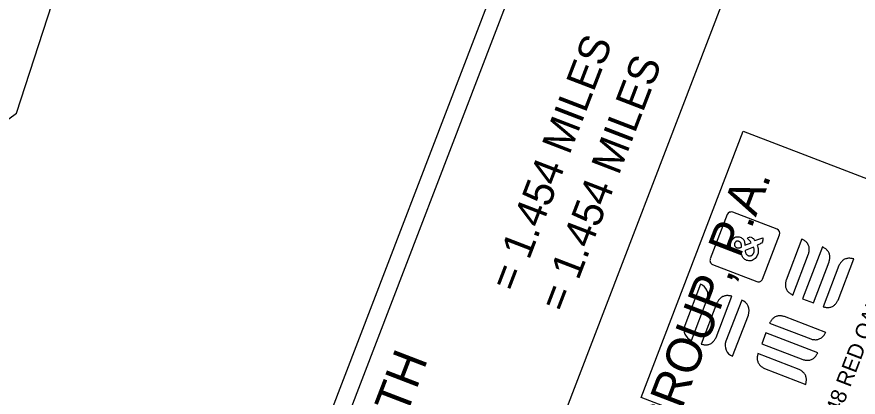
# Model space of a CAD drawing. Extents: x 1015221 to 1064345, y 619216 to 647967.
# Drawn here: x 1023380 to 1025328, y 638817 to 639697 of the extents above; entities that cross this region are included whole.
import ezdxf

# ---------------------------------------------------------------- set-up
doc = ezdxf.new("R2010")
doc.units = 0
for name, color, linetype in [('Old_Level_8', 7, 'Continuous'), ('Scratch_Level_2', 7, 'Continuous'), ('Sheet Data Field CELL', 7, 'Continuous'), ('Sheet Data Text CELL', 7, 'Continuous'), ('Sheet Title CELL', 7, 'Continuous')]:
    doc.layers.add(name, color=color, linetype=linetype)

msp = doc.modelspace()

# ---------------------------------------------------------------- linework, layer by layer
at = {"layer": 'Scratch_Level_2'}
msp.add_lwpolyline([(1020895.4, 635853.8), (1022473.8, 638805.7), (1023379.2, 639473.6), (1023843, 640900.1), (1023637.3, 641036.3), (1023148.3, 642068.8), (1023188.2, 643043.1), (1024411.5, 644926.1), (1023531, 645498.1), (1022160.6, 643388.7), (1022151.2, 643382.8), (1022046.3, 641942.6), (1021939, 640556.9), (1021513.5, 639679.1), (1020439.2, 638632.2), (1020121.4, 637513.2), (1020059.5, 637223.8), (1019861.3, 636035.8)], close=True, dxfattribs=at)
at = {"layer": 'Sheet Data Text CELL'}
for p, q in [((1025025.2, 639239), (1024985.7, 639136.4)), ((1025140.4, 639205.2), (1025037.7, 639244.7)), ((1025106.5, 639090), (1025146, 639192.6)), ((1024991.3, 639123.8), (1025094, 639084.4))]:
    msp.add_line(p, q, dxfattribs=at)
for points in [[(1024825.5, 638816.3), (1025062.2, 639432.5), (1025713.1, 639182.4), (1025476.4, 638566.2)], [(1025052.1, 639177.2), (1025051.5, 639177.3), (1025050.9, 639177.4), (1025050.4, 639177.5), (1025049.8, 639177.6), (1025049.2, 639177.7), (1025048.6, 639177.7), (1025048, 639177.6), (1025047.5, 639177.5), (1025046.9, 639177.3), (1025046.3, 639177.1), (1025045.8, 639176.8), (1025045.3, 639176.5), (1025044.8, 639176.2), (1025044.4, 639175.8), (1025044, 639175.3), (1025043.6, 639174.9), (1025043.3, 639174.4), (1025043, 639173.9), (1025042.7, 639173.3), (1025042.5, 639172.8), (1025042.3, 639172.2), (1025042.1, 639171.7), (1025042, 639171.1), (1025041.9, 639170.5), (1025041.9, 639169.9), (1025041.9, 639169.3), (1025042, 639168.7), (1025042.1, 639168.1), (1025042.2, 639167.6), (1025042.4, 639167), (1025042.7, 639166.4), (1025042.9, 639165.9), (1025043.3, 639165.4), (1025043.7, 639165), (1025044.1, 639164.6), (1025044.5, 639164.2), (1025045, 639163.9), (1025045.5, 639163.6), (1025046, 639163.3), (1025046.5, 639163), (1025047.1, 639162.7), (1025047.2, 639162.6), (1025047.7, 639162.5), (1025048.2, 639162.4), (1025048.7, 639162.2), (1025049.1, 639162.1), (1025049.6, 639162), (1025050.1, 639162), (1025050.6, 639161.9), (1025051.1, 639161.9), (1025051.5, 639162), (1025052, 639162), (1025052.5, 639162.1), (1025053, 639162.2), (1025053.5, 639162.3), (1025054, 639162.4), (1025054.4, 639162.5), (1025054.9, 639162.7), (1025055.4, 639162.8), (1025055.8, 639162.9), (1025056.3, 639163.1), (1025057.2, 639163.4), (1025058.1, 639163.8), (1025058.1, 639165.1), (1025058.1, 639165.8), (1025058.1, 639166.4), (1025058, 639167.1), (1025058, 639167.8), (1025057.9, 639168.5), (1025057.8, 639169.1), (1025057.7, 639169.8), (1025057.6, 639170.5), (1025057.4, 639171.1), (1025057.2, 639171.8), (1025057, 639172.5), (1025056.7, 639173.1), (1025056.4, 639173.7), (1025056, 639174.2), (1025055.6, 639174.7), (1025055.1, 639175.2), (1025054.6, 639175.6), (1025054, 639176), (1025053.5, 639176.4), (1025052.9, 639176.7), (1025052.3, 639177.1)]]:
    msp.add_lwpolyline(points, close=True, dxfattribs=at)
for points in [[(1025025.2, 639239), (1025025.2, 639239), (1024985.7, 639136.4)], [(1025033.2, 639245.2), (1025033.2, 639245.2), (1025032.5, 639245.1), (1025031.9, 639245), (1025031.2, 639244.8), (1025030.6, 639244.6), (1025030, 639244.3), (1025029.4, 639244), (1025028.8, 639243.7), (1025028.3, 639243.3), (1025028.2, 639243.1)], [(1025140.4, 639205.2), (1025037.7, 639244.7)], [(1025094.5, 639168.3), (1025095.3, 639165.8), (1025096.1, 639163.3), (1025096.7, 639160.7), (1025097, 639158.1), (1025097.1, 639155.5), (1025096.8, 639152.8), (1025096.4, 639150.2), (1025095.7, 639147.7), (1025094.8, 639145.2), (1025093.6, 639142.8), (1025092.2, 639140.6), (1025089.6, 639137.5), (1025087.6, 639135.7), (1025085.4, 639134.2), (1025083, 639133), (1025080.5, 639132.3), (1025077.9, 639132), (1025075.3, 639132.2), (1025072.7, 639132.6), (1025070, 639133.1), (1025067.9, 639134.2), (1025066.1, 639135.3), (1025064.3, 639136.5), (1025062.8, 639138), (1025061.5, 639139.6), (1025060.3, 639141.5), (1025059.5, 639143.5), (1025058.8, 639145.5), (1025058.3, 639147.6), (1025058, 639149.7), (1025057.8, 639151.8), (1025056.4, 639152.5), (1025054.5, 639152.1), (1025052.6, 639151.7), (1025050.6, 639151.5), (1025048.7, 639151.5), (1025046.7, 639151.7), (1025044.8, 639152.2), (1025042.9, 639152.7), (1025041.6, 639153.5), (1025039.3, 639154.9), (1025037.2, 639156.5), (1025035.5, 639158.4), (1025034.1, 639160.6), (1025033.2, 639163.1), (1025032.7, 639165.8), (1025032.5, 639168.4), (1025032.7, 639171.1), (1025033.2, 639173.7), (1025034, 639176.2), (1025035.1, 639178.6), (1025036.5, 639180.8), (1025038.1, 639182.9), (1025040.1, 639184.7), (1025042.3, 639186.2), (1025044.8, 639187.3), (1025047.3, 639187.8), (1025049.9, 639187.8), (1025052.5, 639187.5), (1025055.2, 639186.9), (1025057.2, 639185.9), (1025059, 639184.8), (1025060.6, 639183.5), (1025062.1, 639182.1), (1025063.3, 639180.4), (1025064.2, 639178.5), (1025064.9, 639176.5), (1025065.4, 639174.5), (1025065.8, 639172.4), (1025066, 639170.4), (1025066.1, 639168.3), (1025080.9, 639173.7), (1025079.7, 639175.2), (1025078.6, 639176.7), (1025077.4, 639178.2), (1025076.2, 639179.6), (1025075, 639181.1), (1025073.7, 639182.5), (1025072.4, 639183.9), (1025072.7, 639185.5), (1025073.9, 639186.2), (1025076.4, 639187.1), (1025078.5, 639187.3), (1025080.5, 639186.9), (1025082.4, 639186.1), (1025084, 639184.9), (1025085.6, 639183.5), (1025086.7, 639182), (1025087.8, 639180.5), (1025088.9, 639178.9), (1025107.5, 639185.1)], [(1025106.5, 639090), (1025146, 639192.6)], [(1025052.1, 639177.2), (1025051.5, 639177.3), (1025050.9, 639177.4), (1025050.4, 639177.5), (1025049.8, 639177.6), (1025049.2, 639177.7), (1025048.6, 639177.7), (1025048, 639177.6), (1025047.5, 639177.5), (1025046.9, 639177.3), (1025046.3, 639177.1), (1025045.8, 639176.8), (1025045.3, 639176.5), (1025044.8, 639176.2), (1025044.4, 639175.8), (1025044, 639175.3), (1025043.6, 639174.9), (1025043.3, 639174.4), (1025043, 639173.9), (1025042.7, 639173.3), (1025042.5, 639172.8), (1025042.3, 639172.2), (1025042.1, 639171.7), (1025042, 639171.1), (1025041.9, 639170.5), (1025041.9, 639169.9), (1025041.9, 639169.3), (1025042, 639168.7), (1025042.1, 639168.1), (1025042.2, 639167.6), (1025042.4, 639167), (1025042.7, 639166.4), (1025042.9, 639165.9), (1025043.3, 639165.4), (1025043.7, 639165), (1025044.1, 639164.6), (1025044.5, 639164.2), (1025045, 639163.9), (1025045.5, 639163.6), (1025046, 639163.3), (1025046.5, 639163), (1025047.1, 639162.7), (1025047.2, 639162.6), (1025047.7, 639162.5), (1025048.2, 639162.4), (1025048.7, 639162.2), (1025049.1, 639162.1), (1025049.6, 639162), (1025050.1, 639162), (1025050.6, 639161.9), (1025051.1, 639161.9), (1025051.5, 639162), (1025052, 639162), (1025052.5, 639162.1), (1025053, 639162.2), (1025053.5, 639162.3), (1025054, 639162.4), (1025054.4, 639162.5), (1025054.9, 639162.7), (1025055.4, 639162.8), (1025055.8, 639162.9), (1025056.3, 639163.1), (1025057.2, 639163.4), (1025058.1, 639163.8), (1025058.1, 639165.1), (1025058.1, 639165.8), (1025058.1, 639166.4), (1025058, 639167.1), (1025058, 639167.8), (1025057.9, 639168.5), (1025057.8, 639169.1), (1025057.7, 639169.8), (1025057.6, 639170.5), (1025057.4, 639171.1), (1025057.2, 639171.8), (1025057, 639172.5), (1025056.7, 639173.1), (1025056.4, 639173.7), (1025056, 639174.2), (1025055.6, 639174.7), (1025055.1, 639175.2), (1025054.6, 639175.6), (1025054, 639176), (1025053.5, 639176.4), (1025052.9, 639176.7), (1025052.3, 639177.1), (1025052.1, 639177.2)], [(1025107.6, 639184.3), (1025107.8, 639182.1), (1025107.7, 639179.9), (1025107.1, 639177.7), (1025106.5, 639176.3), (1025104.2, 639173.4), (1025102.4, 639172), (1025100.5, 639170.8), (1025094.5, 639168.3)], [(1025107.5, 639185.1), (1025107.6, 639184.3)], [(1025211.8, 639171.2), (1025210.8, 639172.7), (1025209.7, 639174.1), (1025208.4, 639175.5), (1025207.1, 639176.7), (1025205.7, 639177.9), (1025204.3, 639178.9), (1025202.8, 639179.9), (1025201.2, 639180.9), (1025199.6, 639181.8), (1025198, 639182.8), (1025161.4, 639087.5), (1025161.1, 639085.7), (1025160.7, 639083.9), (1025160.4, 639082.1), (1025160.1, 639080.3), (1025159.9, 639078.5), (1025159.8, 639076.7), (1025159.9, 639074.9), (1025160.1, 639073.1), (1025160.4, 639071.3), (1025160.9, 639069.5), (1025161.5, 639067.8), (1025162.2, 639066.1), (1025163.1, 639064.5), (1025164.1, 639062.9), (1025165.2, 639061.5), (1025166.4, 639060.1), (1025167.8, 639058.9), (1025169.1, 639057.8), (1025170.6, 639056.7), (1025172.1, 639055.7), (1025173.7, 639054.7), (1025175.3, 639053.8), (1025176.8, 639052.9), (1025213.5, 639148.1), (1025213.8, 639149.9), (1025214.2, 639151.7), (1025214.5, 639153.5), (1025214.8, 639155.3), (1025215, 639157.1), (1025215, 639158.9), (1025215, 639160.7), (1025214.8, 639162.5), (1025214.5, 639164.3), (1025214, 639166.1), (1025213.4, 639167.8), (1025212.6, 639169.5), (1025211.8, 639171.2)], [(1025073.8, 639144.2), (1025074.6, 639144), (1025075.3, 639143.9), (1025076.1, 639143.7), (1025076.8, 639143.7), (1025077.5, 639143.6), (1025078.2, 639143.6), (1025079, 639143.7), (1025080.4, 639144.1), (1025081.7, 639144.7), (1025082.9, 639145.6), (1025083.5, 639146.1), (1025084, 639146.6), (1025084.5, 639147.2), (1025085, 639147.8), (1025085.4, 639148.4), (1025085.8, 639149), (1025086.1, 639149.6), (1025086.5, 639150.3), (1025086.7, 639151), (1025087, 639151.7), (1025087.2, 639152.4), (1025087.4, 639153.1), (1025087.5, 639153.8), (1025087.6, 639154.6), (1025087.7, 639155.3), (1025087.7, 639156), (1025087.7, 639156.8), (1025087.6, 639157.5), (1025087.6, 639158.2), (1025087.5, 639159), (1025087.3, 639159.7), (1025087, 639161.1), (1025086.6, 639162.5), (1025086.1, 639163.9), (1025066.6, 639156.3), (1025066.8, 639155), (1025066.9, 639153.7), (1025067.2, 639152.5), (1025067.5, 639151.2), (1025067.9, 639150), (1025068.5, 639148.8), (1025069.1, 639147.7), (1025070, 639146.7), (1025070.9, 639145.9), (1025072, 639145.2), (1025072.5, 639144.8), (1025073.1, 639144.5), (1025073.8, 639144.2)], [(1025254.8, 639158.4), (1025253.4, 639159.6), (1025251.9, 639160.6), (1025250.4, 639161.6), (1025248.9, 639162.6), (1025247.3, 639163.5), (1025245.7, 639164.5), (1025199.5, 639044.2), (1025224.5, 639034.6), (1025261.1, 639129.8), (1025261.5, 639131.6), (1025261.8, 639133.4), (1025262.2, 639135.2), (1025262.4, 639137), (1025262.6, 639138.8), (1025262.7, 639140.6), (1025262.6, 639142.4), (1025262.5, 639144.2), (1025262.1, 639146), (1025261.7, 639147.8), (1025261, 639149.5), (1025260.3, 639151.2), (1025259.4, 639152.8), (1025258.4, 639154.4), (1025257.3, 639155.8), (1025256.1, 639157.2), (1025254.8, 639158.4)], [(1024985.3, 639130.7), (1024985.4, 639130.5), (1024985.5, 639129.9), (1024985.8, 639129.3), (1024986, 639128.6), (1024986.4, 639128), (1024986.7, 639127.5), (1024986.9, 639127.3)], [(1025309.3, 639138.1), (1025307.5, 639138.1), (1025305.7, 639138.1), (1025303.9, 639137.9), (1025302.1, 639137.6), (1025300.4, 639137.1), (1025298.6, 639136.5), (1025296.9, 639135.7), (1025295.3, 639134.9), (1025293.8, 639133.9), (1025292.3, 639132.8), (1025291, 639131.5), (1025289.8, 639130.2), (1025288.6, 639128.8), (1025287.6, 639127.4), (1025286.5, 639125.9), (1025285.6, 639124.3), (1025284.6, 639122.7), (1025283.7, 639121.1), (1025247.1, 639025.9), (1025248.9, 639025.5), (1025250.7, 639025.1), (1025252.5, 639024.8), (1025254.3, 639024.5), (1025256.1, 639024.3), (1025257.9, 639024.3), (1025259.7, 639024.3), (1025261.5, 639024.5), (1025263.3, 639024.8), (1025265.1, 639025.3), (1025266.8, 639025.9), (1025268.5, 639026.7), (1025270.1, 639027.5), (1025271.7, 639028.5), (1025273.1, 639029.6), (1025274.5, 639030.9), (1025275.7, 639032.2), (1025276.8, 639033.6), (1025277.9, 639035), (1025278.9, 639036.5), (1025279.9, 639038.1), (1025280.8, 639039.7), (1025281.7, 639041.3), (1025318.3, 639136.5), (1025316.5, 639136.9), (1025314.7, 639137.3), (1025312.9, 639137.6), (1025311.1, 639137.9), (1025309.3, 639138.1)], [(1024991.3, 639123.8), (1025094, 639084.4)], [(1024963.3, 639078), (1024926.7, 638982.7)], [(1025019.8, 639051.1), (1025018, 639050.7), (1025016.3, 639050), (1025014.6, 639049.3), (1025012.9, 639048.4), (1025011.4, 639047.4), (1025010, 639046.3), (1025008.6, 639045.1), (1025007.4, 639043.8), (1025006.2, 639042.4), (1025005.2, 639040.9), (1025004.2, 639039.4), (1025003.2, 639037.9), (1025002.3, 639036.3), (1025001.3, 639034.7), (1024964.7, 638939.4), (1024966.5, 638939), (1024968.3, 638938.7), (1024970.1, 638938.3), (1024971.9, 638938.1), (1024973.7, 638937.9), (1024975.5, 638937.8), (1024977.3, 638937.8), (1024979.1, 638938), (1024980.9, 638938.4), (1024982.7, 638938.8), (1024984.4, 638939.5), (1024986.1, 638940.2), (1024987.7, 638941.1), (1024989.3, 638942.1), (1024990.7, 638943.2), (1024992.1, 638944.4), (1024993.3, 638945.7), (1024994.4, 638947.1), (1024995.5, 638948.6), (1024996.5, 638950.1), (1024997.5, 638951.6), (1024998.4, 638953.2), (1024999.4, 638954.8), (1025036, 639050.1), (1025034.2, 639050.5), (1025032.4, 639050.8), (1025030.6, 639051.2), (1025028.8, 639051.4), (1025027, 639051.6), (1025025.2, 639051.7), (1025023.4, 639051.6), (1025021.6, 639051.5), (1025019.8, 639051.1)], [(1024942.1, 638948.1), (1024978.7, 639043.4)], [(1025058.6, 639041.4), (1025022, 638946.1)], [(1025037.4, 638911.5), (1025074, 639006.8)], [(1025157.8, 639003.3), (1025156, 639003.7), (1025154.2, 639004), (1025152.4, 639004.3), (1025150.6, 639004.6), (1025148.8, 639004.8), (1025147, 639004.9), (1025145.2, 639004.8), (1025143.4, 639004.6), (1025141.6, 639004.3), (1025139.8, 639003.8), (1025138.1, 639003.2), (1025136.4, 639002.5), (1025134.8, 639001.6), (1025133.2, 639000.6), (1025131.8, 638999.5), (1025130.5, 638998.3), (1025129.2, 638997), (1025128.1, 638995.6), (1025127, 638994.1), (1025126, 638992.6), (1025125, 638991), (1025124.1, 638989.5), (1025123.2, 638987.9), (1025218.5, 638951.3), (1025220.3, 638950.9), (1025222.1, 638950.5), (1025223.9, 638950.2), (1025225.7, 638949.9), (1025227.5, 638949.8), (1025229.3, 638949.7), (1025231.1, 638949.7), (1025232.8, 638949.9), (1025234.6, 638950.2), (1025236.4, 638950.7), (1025238.2, 638951.3), (1025239.8, 638952.1), (1025241.5, 638952.9), (1025243, 638953.9), (1025244.5, 638955.1), (1025245.8, 638956.3), (1025247, 638957.6), (1025248.2, 638959), (1025249.2, 638960.4), (1025250.2, 638961.9), (1025251.2, 638963.5), (1025252.2, 638965.1), (1025253.1, 638966.7), (1025157.8, 639003.3)], [(1025114.5, 638965.2), (1025104.9, 638940.2), (1025200.1, 638903.6), (1025201.9, 638903.2), (1025203.7, 638902.9), (1025205.5, 638902.6), (1025207.3, 638902.3), (1025209.1, 638902.1), (1025210.9, 638902), (1025212.7, 638902.1), (1025214.5, 638902.3), (1025216.3, 638902.6), (1025218.1, 638903.1), (1025219.9, 638903.7), (1025221.5, 638904.4), (1025223.2, 638905.3), (1025224.7, 638906.3), (1025226.2, 638907.4), (1025227.5, 638908.6), (1025228.7, 638909.9), (1025229.9, 638911.3), (1025230.9, 638912.8), (1025231.9, 638914.3), (1025232.9, 638915.9), (1025233.8, 638917.4), (1025234.8, 638919), (1025114.5, 638965.2)], [(1025096.2, 638917.6), (1025095.8, 638915.8), (1025095.4, 638914), (1025095.1, 638912.2), (1025094.8, 638910.4), (1025094.7, 638908.6), (1025094.6, 638906.8), (1025094.6, 638905), (1025094.8, 638903.2), (1025095.1, 638901.4), (1025095.6, 638899.6), (1025096.2, 638897.9), (1025097, 638896.2), (1025097.9, 638894.6), (1025098.9, 638893), (1025100, 638891.6), (1025101.2, 638890.3), (1025102.5, 638889), (1025103.9, 638887.9), (1025105.3, 638886.8), (1025106.9, 638885.8), (1025108.4, 638884.8), (1025110, 638883.9), (1025111.6, 638883), (1025206.9, 638846.4), (1025207.2, 638848.2), (1025207.6, 638850), (1025207.9, 638851.8), (1025208.2, 638853.6), (1025208.4, 638855.4), (1025208.4, 638857.2), (1025208.4, 638859), (1025208.2, 638860.8), (1025207.9, 638862.6), (1025207.4, 638864.3), (1025206.8, 638866.1), (1025206.1, 638867.8), (1025205.2, 638869.4), (1025204.2, 638870.9), (1025203.1, 638872.4), (1025201.9, 638873.7), (1025200.5, 638874.9), (1025199.2, 638876.1), (1025197.7, 638877.2), (1025196.2, 638878.2), (1025194.6, 638879.1), (1025193, 638880.1), (1025191.5, 638881), (1025096.2, 638917.6)]]:
    msp.add_lwpolyline(points, dxfattribs=at)
for centre, radius, start, end in [((1025034.3, 639235.5), 9.77, 69.4028, 158.8148), ((1025034.3, 639235.5), 9.77, 69.4028, 158.8148), ((1025136.9, 639196.1), 9.77, 339.1512, 68.5632), ((1025136.9, 639196.1), 9.77, 339.1512, 68.5632), ((1024994.8, 639132.9), 9.7, 158.9773, 248.983), ((1024994.8, 639132.9), 9.7, 158.9773, 248.983), ((1025097.5, 639093.4), 9.7, 248.983, 338.9887), ((1025097.5, 639093.4), 9.7, 248.983, 338.9887), ((1024953.7, 639053), 26.8, 338.983, 68.983), ((1025049, 639016.4), 26.8, 338.983, 68.983), ((1024951.7, 638973.1), 26.8, 158.983, 248.983), ((1025047, 638936.5), 26.8, 158.983, 248.983)]:
    msp.add_arc(centre, radius, start, end, dxfattribs=at)
at = {"layer": 'Sheet Title CELL'}
for p, q in [((1022495.1, 634584.7), (1026569.3, 645189)), ((1023508, 637109.4), (1024598.3, 639947.1)), ((1023914.2, 636867.6), (1025061.8, 639854.7))]:
    msp.add_line(p, q, dxfattribs=at)

# ---------------------------------------------------------------- texts
at = {"layer": 'Old_Level_8'}
msp.add_text('FOR THE NORTH CAROLINA DEPARTMENT OF TRANSPORTATION', height=51.593, rotation=68.983, dxfattribs=at).set_placement((1024922, 636920.4))
at = {"layer": 'Sheet Data Field CELL'}
for p in [(1024537.2, 639056.9), (1024651.4, 639009.8)]:
    msp.add_text('= 1.454 MILES', height=70.001, rotation=68.983, dxfattribs=at).set_placement(p)
at = {"layer": 'Sheet Data Text CELL'}
for s, height, p in [('SUNGATE DESIGN GROUP, P.A.', 81.268, (1024530.3, 637772.4)), ('8848 RED OAK BLVD', 36.237, (1025266.3, 638724.7))]:
    msp.add_text(s, height=height, rotation=68.983, dxfattribs=at).set_placement(p)
at = {"layer": 'Sheet Title CELL'}
msp.add_text('PROJECT LENGTH', height=79.997, rotation=68.983, dxfattribs=at).set_placement((1023987.5, 638005.8))

doc.saveas('drawing.dxf')
